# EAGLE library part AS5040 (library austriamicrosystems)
10-BIT PROGRAMMABLE MAGNETIC ROTARY ENCODER Source: www.austriamicrosystems.com .. AS5040DataSheetRev12.pdf
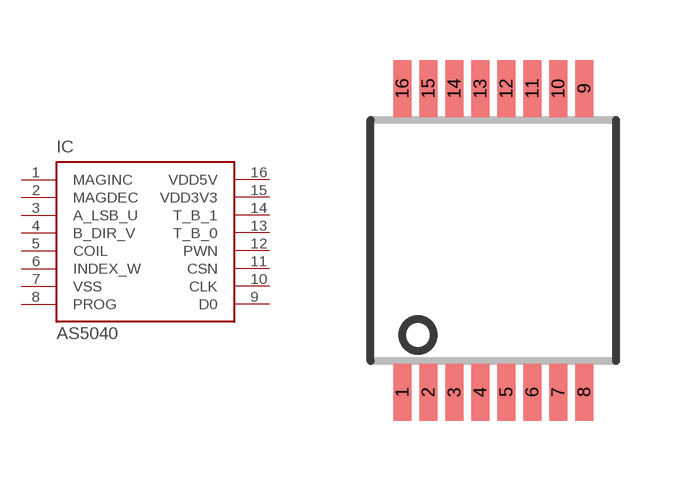
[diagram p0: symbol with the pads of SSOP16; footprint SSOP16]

Designator prefix IC

## AS5040 (MPN: AS5040ASSU; OC_FARNELL: 1630800; OC_NEWARK: 59P4059)  [SSOP16]
1  MAGINC  hiz
2  MAGDEC  hiz
3  A_LSB_U  out
4  B_DIR_V  out
5  COIL  nc
6  INDEX_W  out
7  VSS  pas
8  PROG  in
9  D0  hiz
10  CLK  in
11  CSN  in
12  PWN  pas
13  T_B_0  nc
14  T_B_1  nc
15  VDD3V3  pas
16  VDD5V  pas

## Footprint SSOP16 (pad centres in mm)
Small Shrink Outline Package SSOP 16 (5.3mm x 6.2mm) Source: www.austriamicrosystems.com .. AS5040DataSheetRev12.pdf
smd 0.46 x 1.43: 1 -2.275,-3.795; 2 -1.625,-3.795; 3 -0.975,-3.795; 4 -0.325,-3.795; 5 0.325,-3.795; 6 0.975,-3.795; 7 1.625,-3.795; 8 2.275,-3.795; 9 2.275,3.795; 10 1.625,3.795; 11 0.975,3.795; 12 0.325,3.795; 13 -0.325,3.795; 14 -0.975,3.795; 15 -1.625,3.795; 16 -2.275,3.795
